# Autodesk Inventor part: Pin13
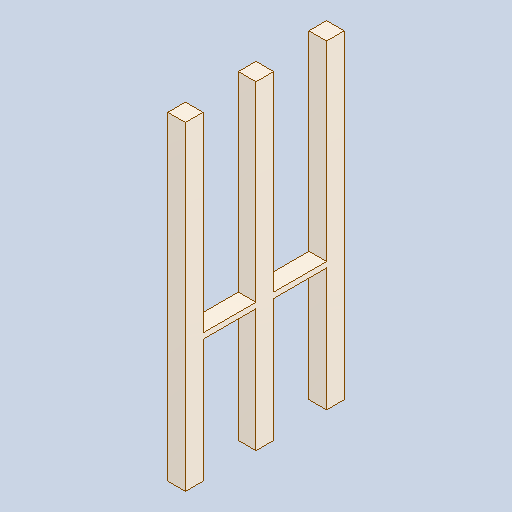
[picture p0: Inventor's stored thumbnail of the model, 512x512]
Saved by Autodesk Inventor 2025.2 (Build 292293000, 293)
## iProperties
Created: 2025-04
Part Number: Pin13
Material: Generic
Description: PART--DESC
Document SubType Name: Modeling
Designer: BennF
Density: 1 g/cm^3
Appearance: Default
Author: BennF
Revision Number: NONE
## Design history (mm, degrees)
feature "Solid"
body "Solid1"
